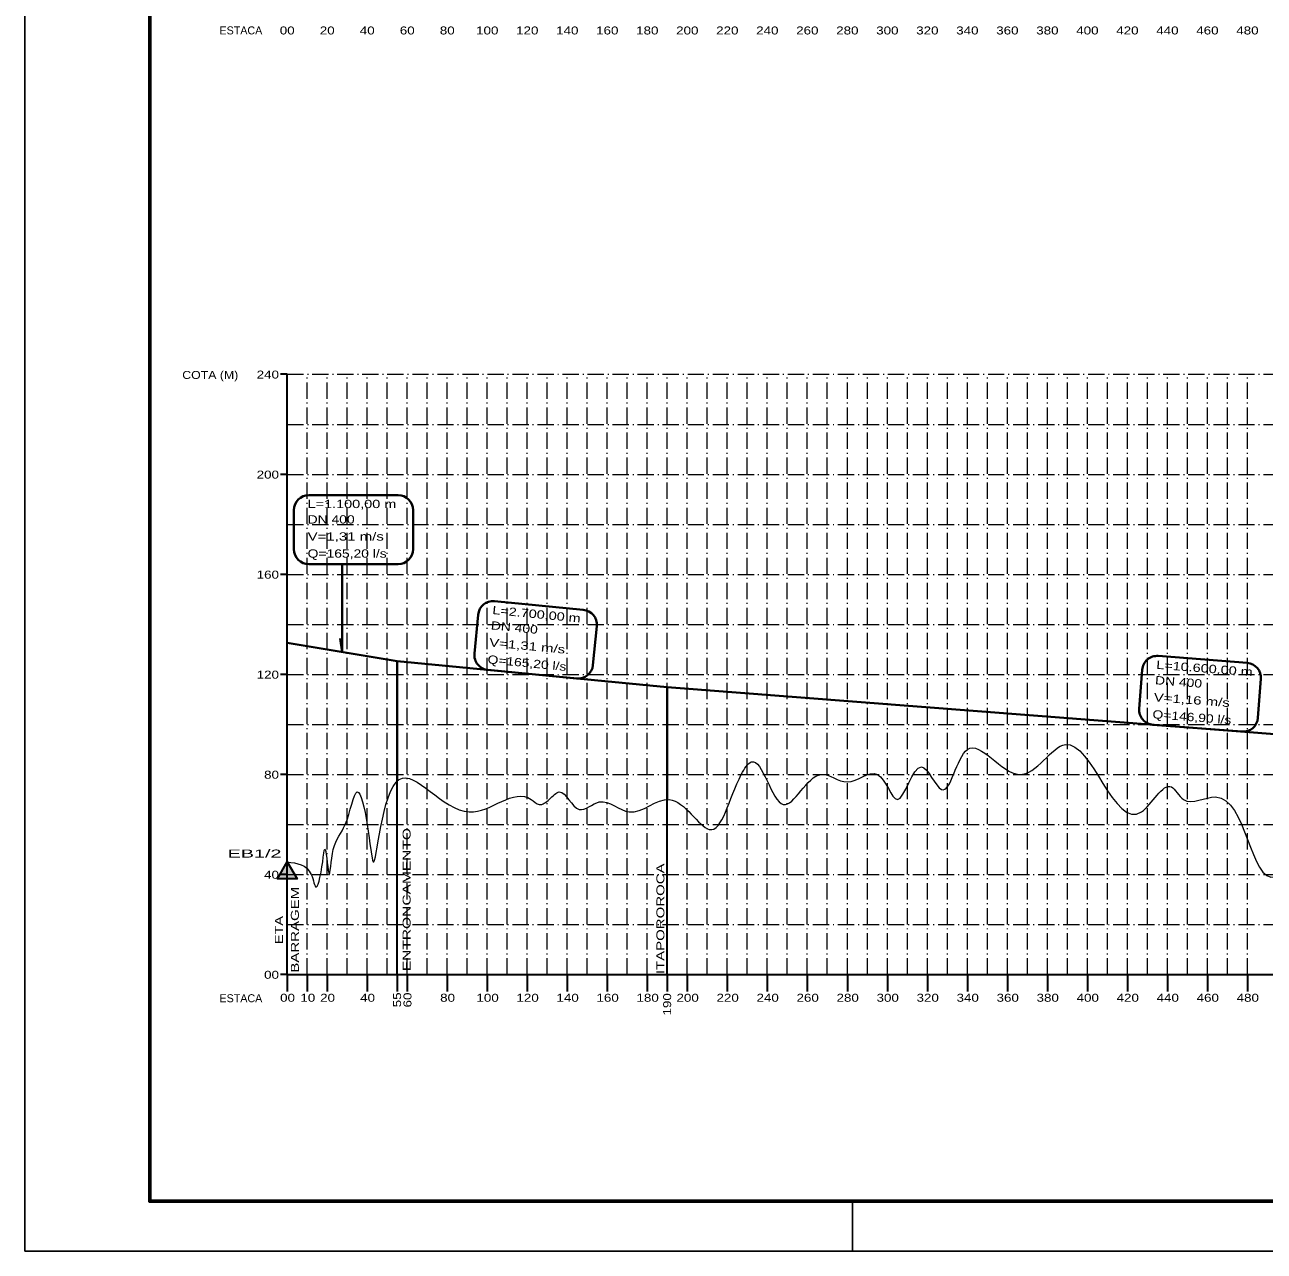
# Model space of a CAD drawing. Extents: x 0 to 1682, y 0 to 1188.
# Drawn here: x -0.2 to 495.5, y -0.1 to 490.3 of the extents above; entities that cross this region are included whole.
import ezdxf
from ezdxf.enums import TextEntityAlignment as Align

# ---------------------------------------------------------------- set-up
doc = ezdxf.new("R2010")
doc.units = 0
doc.header["$LTSCALE"] = 1.3
doc.linetypes.add('DOT_DASHED', pattern=[7.7, 5, -1.2, 0.3, -1.2])
for name, color, linetype, lineweight in [('1', 7, 'DOT_DASHED', 13), ('56', 7, 'Continuous', 13), ('62', 7, 'Continuous', 13), ('63', 7, 'Continuous', 25), ('9', 7, 'Continuous', 40)]:
    doc.layers.add(name, color=color, linetype=linetype, lineweight=lineweight)
doc.layers.add('24', color=7, linetype='Continuous')

msp = doc.modelspace()

# ---------------------------------------------------------------- hatches: boundary and pattern name
at = {"layer": '62'}
msp.add_hatch(color=256, dxfattribs=at).paths.add_polyline_path([(104.775, 155.521), (108.721, 148.783), (100.912, 148.734)])

# ---------------------------------------------------------------- linework, layer by layer
at = {"layer": '1'}
for p, q in [((104.775, 350.521), (1145.575, 350.521)), ((112.775, 110.521), (112.775, 350.521)), ((120.775, 110.521), (120.775, 350.521)), ((128.775, 110.521), (128.775, 350.521)), ((136.775, 110.521), (136.775, 350.521)), ((144.775, 110.521), (144.775, 350.521)), ((152.775, 110.521), (152.775, 350.521)), ((160.775, 110.521), (160.775, 350.521)), ((168.775, 110.521), (168.775, 350.521)), ((176.775, 110.521), (176.775, 350.521)), ((184.775, 110.521), (184.775, 350.521)), ((192.775, 110.521), (192.775, 350.521)), ((200.775, 110.521), (200.775, 350.521)), ((208.775, 110.521), (208.775, 350.521)), ((216.775, 110.521), (216.775, 350.521)), ((224.775, 110.521), (224.775, 350.521)), ((232.775, 110.521), (232.775, 350.521)), ((240.775, 110.521), (240.775, 350.521)), ((248.775, 110.521), (248.775, 350.521)), ((256.775, 110.521), (256.775, 350.521)), ((264.775, 110.521), (264.775, 350.521)), ((272.775, 110.521), (272.775, 350.521)), ((280.775, 110.521), (280.775, 350.521)), ((288.775, 110.521), (288.775, 350.521)), ((296.775, 110.521), (296.775, 350.521)), ((304.775, 110.521), (304.775, 350.521)), ((312.775, 110.521), (312.775, 350.521)), ((320.775, 110.521), (320.775, 350.521)), ((328.775, 110.521), (328.775, 350.521)), ((336.775, 110.521), (336.775, 350.521)), ((344.775, 110.521), (344.775, 350.521)), ((352.775, 110.521), (352.775, 350.521)), ((360.775, 110.521), (360.775, 350.521)), ((368.775, 110.521), (368.775, 350.521)), ((376.775, 110.521), (376.775, 350.521)), ((384.775, 110.521), (384.775, 350.521)), ((392.775, 110.521), (392.775, 350.521)), ((400.775, 110.521), (400.775, 350.521)), ((408.775, 110.521), (408.775, 350.521)), ((416.775, 110.521), (416.775, 350.521)), ((424.775, 110.521), (424.775, 350.521)), ((432.775, 110.521), (432.775, 350.521)), ((440.775, 110.521), (440.775, 350.521)), ((448.775, 110.521), (448.775, 350.521)), ((456.775, 110.521), (456.775, 350.521)), ((464.775, 110.521), (464.775, 350.521)), ((472.775, 110.521), (472.775, 350.521)), ((480.775, 110.521), (480.775, 350.521)), ((488.775, 110.521), (488.775, 350.521)), ((104.775, 330.521), (1145.575, 330.521)), ((104.775, 310.521), (1145.575, 310.521)), ((104.775, 290.521), (1145.575, 290.521)), ((104.775, 270.521), (1145.575, 270.521)), ((104.775, 250.521), (1145.575, 250.521)), ((104.775, 230.521), (1145.575, 230.521)), ((104.775, 210.521), (1145.575, 210.521)), ((104.775, 190.521), (1145.575, 190.521)), ((104.775, 170.521), (1145.575, 170.521)), ((104.775, 150.521), (1145.575, 150.521)), ((104.775, 130.521), (1145.575, 130.521))]:
    msp.add_line(p, q, dxfattribs=at)
at = {"layer": '56'}
msp.add_spline([(104.775, 155.521), (114.375, 150.521), (116.375, 145.521), (117.875, 149.271), (119.975, 160.521), (121.575, 150.521), (123.175, 160.521), (127.975, 170.521), (132.775, 183.521), (136.775, 170.521), (139.175, 155.521), (149.575, 188.521), (177.575, 175.521), (202.375, 180.521), (205.575, 178.521), (209.575, 180.521), (213.575, 183.521), (221.575, 176.521), (229.575, 179.521), (241.575, 175.521), (257.575, 180.521), (273.575, 168.521), (286.375, 190.521), (290.375, 195.521), (303.175, 178.521), (318.375, 190.521), (328.775, 187.521), (340.775, 190.521), (348.775, 180.521), (358.375, 193.521), (366.375, 184.521), (376.775, 200.521), (397.575, 190.521), (415.975, 202.521), (446.375, 175.521), (458.375, 185.521), (463.175, 180.521), (475.975, 181.521), (499.975, 149.521), (508.375, 153.521), (524.375, 150.521), (541.975, 165.521), (561.975, 191.521), (569.975, 180.521), (617.975, 143.521), (647.575, 180.521), (655.975, 185.521), (758.375, 160.521), (767.975, 148.521), (774.375, 155.521), (778.375, 158.521), (790.375, 150.521), (798.375, 156.521), (802.375, 150.521), (818.375, 150.521), (858.375, 140.521), (874.375, 128.521), (898.375, 160.521), (910.375, 145.521), (915.175, 153.521), (935.175, 125.521), (940.775, 130.521), (948.775, 127.521), (956.775, 130.521), (975.975, 120.521), (984.775, 118.521), (995.175, 125.521), (1023.975, 118.521), (1029.575, 120.521), (1033.575, 118.521), (1040.775, 123.521), (1048.775, 118.521), (1068.775, 125.521), (1084.775, 118.521), (1091.175, 123.521), (1095.175, 120.521), (1099.975, 122.521), (1107.975, 117.521), (1114.375, 120.521), (1130.375, 118.521), (1145.575, 118.521)], degree=3, dxfattribs=at)
at = {"layer": '62', "lineweight": 35}
for p, q in [((104.775, 350.521), (102.044, 350.521)), ((104.607, 350.521), (104.775, 350.521)), ((104.775, 110.521), (104.775, 350.521)), ((104.607, 340.521), (104.775, 340.521)), ((104.607, 330.521), (104.775, 330.521)), ((104.607, 320.521), (104.775, 320.521)), ((104.775, 310.521), (102.044, 310.521)), ((104.607, 310.521), (104.775, 310.521)), ((104.607, 300.521), (104.775, 300.521)), ((104.607, 290.521), (104.775, 290.521)), ((104.607, 280.521), (104.775, 280.521)), ((104.775, 270.521), (102.044, 270.521)), ((104.607, 270.521), (104.775, 270.521)), ((104.607, 260.521), (104.775, 260.521)), ((104.607, 250.521), (104.775, 250.521)), ((104.607, 240.521), (104.775, 240.521)), ((104.775, 230.521), (102.044, 230.521)), ((104.607, 230.521), (104.775, 230.521)), ((104.607, 220.521), (104.775, 220.521)), ((104.607, 210.521), (104.775, 210.521)), ((104.607, 200.521), (104.775, 200.521)), ((104.775, 190.521), (102.044, 190.521)), ((104.607, 190.521), (104.775, 190.521)), ((148.775, 110.521), (148.775, 188.469)), ((104.607, 180.521), (104.775, 180.521)), ((256.775, 110.521), (256.775, 180.457)), ((104.607, 170.521), (104.775, 170.521)), ((104.607, 160.521), (104.775, 160.521)), ((104.775, 150.521), (102.044, 150.521)), ((104.607, 150.521), (104.775, 150.521)), ((104.607, 140.521), (104.775, 140.521)), ((104.607, 130.521), (104.775, 130.521)), ((104.607, 120.521), (104.775, 120.521)), ((104.775, 110.521), (102.044, 110.521)), ((104.775, 110.521), (104.775, 103.693)), ((104.775, 110.521), (1145.575, 110.521)), ((112.775, 110.521), (112.775, 103.693)), ((120.775, 110.521), (120.775, 103.693)), ((136.775, 110.521), (136.775, 103.693)), ((148.775, 110.521), (148.775, 103.693)), ((152.775, 110.521), (152.775, 103.693)), ((168.775, 110.521), (168.775, 103.693)), ((184.775, 110.521), (184.775, 103.693)), ((200.775, 110.521), (200.775, 103.693)), ((216.775, 110.521), (216.775, 103.693)), ((232.775, 110.521), (232.775, 103.693)), ((248.775, 110.521), (248.775, 103.693)), ((256.775, 110.521), (256.775, 103.693)), ((264.775, 110.521), (264.775, 103.693)), ((280.775, 110.521), (280.775, 103.693)), ((296.775, 110.521), (296.775, 103.693)), ((312.775, 110.521), (312.775, 103.693)), ((328.775, 110.521), (328.775, 103.693)), ((344.775, 110.521), (344.775, 103.693)), ((360.775, 110.521), (360.775, 103.693)), ((376.775, 110.521), (376.775, 103.693)), ((392.775, 110.521), (392.775, 103.693)), ((408.775, 110.521), (408.775, 103.693)), ((424.775, 110.521), (424.775, 103.693)), ((440.775, 110.521), (440.775, 103.693)), ((456.775, 110.521), (456.775, 103.693)), ((472.775, 110.521), (472.775, 103.693)), ((488.775, 110.521), (488.775, 103.693))]:
    msp.add_line(p, q, dxfattribs=at)
at = {"layer": '62'}
for p, q in [((104.607, 348.521), (104.775, 348.521)), ((104.607, 346.521), (104.775, 346.521)), ((104.607, 344.521), (104.775, 344.521)), ((104.607, 342.521), (104.775, 342.521)), ((104.607, 338.521), (104.775, 338.521)), ((104.607, 336.521), (104.775, 336.521)), ((104.607, 334.521), (104.775, 334.521)), ((104.607, 332.521), (104.775, 332.521)), ((104.607, 328.521), (104.775, 328.521)), ((104.607, 326.521), (104.775, 326.521)), ((104.607, 324.521), (104.775, 324.521)), ((104.607, 322.521), (104.775, 322.521)), ((104.607, 318.521), (104.775, 318.521)), ((104.607, 316.521), (104.775, 316.521)), ((104.607, 314.521), (104.775, 314.521)), ((104.607, 312.521), (104.775, 312.521)), ((104.607, 308.521), (104.775, 308.521)), ((104.607, 306.521), (104.775, 306.521)), ((104.607, 304.521), (104.775, 304.521)), ((104.607, 302.521), (104.775, 302.521)), ((104.607, 298.521), (104.775, 298.521)), ((104.607, 296.521), (104.775, 296.521)), ((104.607, 294.521), (104.775, 294.521)), ((104.607, 292.521), (104.775, 292.521)), ((104.607, 288.521), (104.775, 288.521)), ((104.607, 286.521), (104.775, 286.521)), ((104.607, 284.521), (104.775, 284.521)), ((104.607, 282.521), (104.775, 282.521)), ((104.607, 278.521), (104.775, 278.521)), ((104.607, 276.521), (104.775, 276.521)), ((104.607, 274.521), (104.775, 274.521)), ((104.607, 272.521), (104.775, 272.521)), ((104.607, 268.521), (104.775, 268.521)), ((104.607, 266.521), (104.775, 266.521)), ((104.607, 264.521), (104.775, 264.521)), ((104.607, 262.521), (104.775, 262.521)), ((104.607, 258.521), (104.775, 258.521)), ((104.607, 256.521), (104.775, 256.521)), ((104.607, 254.521), (104.775, 254.521)), ((104.607, 252.521), (104.775, 252.521)), ((104.607, 248.521), (104.775, 248.521)), ((104.607, 246.521), (104.775, 246.521)), ((104.607, 244.521), (104.775, 244.521)), ((104.607, 242.521), (104.775, 242.521)), ((104.607, 238.521), (104.775, 238.521)), ((104.607, 236.521), (104.775, 236.521)), ((104.607, 234.521), (104.775, 234.521)), ((104.607, 232.521), (104.775, 232.521)), ((104.607, 228.521), (104.775, 228.521)), ((104.607, 226.521), (104.775, 226.521)), ((104.607, 224.521), (104.775, 224.521)), ((104.607, 222.521), (104.775, 222.521)), ((104.607, 218.521), (104.775, 218.521)), ((104.607, 216.521), (104.775, 216.521)), ((104.607, 214.521), (104.775, 214.521)), ((104.607, 212.521), (104.775, 212.521)), ((104.607, 208.521), (104.775, 208.521)), ((104.607, 206.521), (104.775, 206.521)), ((104.607, 204.521), (104.775, 204.521)), ((104.607, 202.521), (104.775, 202.521)), ((104.607, 198.521), (104.775, 198.521)), ((104.607, 196.521), (104.775, 196.521)), ((104.607, 194.521), (104.775, 194.521)), ((104.607, 192.521), (104.775, 192.521)), ((104.607, 188.521), (104.775, 188.521)), ((104.607, 186.521), (104.775, 186.521)), ((104.607, 184.521), (104.775, 184.521)), ((104.607, 182.521), (104.775, 182.521)), ((104.607, 178.521), (104.775, 178.521)), ((104.607, 176.521), (104.775, 176.521)), ((104.607, 174.521), (104.775, 174.521)), ((104.607, 172.521), (104.775, 172.521)), ((104.607, 168.521), (104.775, 168.521)), ((104.607, 166.521), (104.775, 166.521)), ((104.607, 164.521), (104.775, 164.521)), ((104.607, 162.521), (104.775, 162.521)), ((104.607, 158.521), (104.775, 158.521)), ((104.607, 156.521), (104.775, 156.521)), ((104.607, 154.521), (104.775, 154.521)), ((104.607, 152.521), (104.775, 152.521)), ((104.607, 148.521), (104.775, 148.521)), ((104.607, 146.521), (104.775, 146.521)), ((104.607, 144.521), (104.775, 144.521)), ((104.607, 142.521), (104.775, 142.521)), ((104.607, 138.521), (104.775, 138.521)), ((104.607, 136.521), (104.775, 136.521)), ((104.607, 134.521), (104.775, 134.521)), ((104.607, 132.521), (104.775, 132.521)), ((104.607, 128.521), (104.775, 128.521)), ((104.607, 126.521), (104.775, 126.521)), ((104.607, 124.521), (104.775, 124.521)), ((104.607, 122.521), (104.775, 122.521)), ((104.607, 118.521), (104.775, 118.521)), ((104.607, 116.521), (104.775, 116.521)), ((104.607, 114.521), (104.775, 114.521)), ((104.607, 112.521), (104.775, 112.521))]:
    msp.add_line(p, q, dxfattribs=at)
at = {"layer": '62', "lineweight": 35}
msp.add_lwpolyline([(104.775, 155.521), (108.721, 148.783), (100.912, 148.734)], close=True, dxfattribs=at)
at = {"layer": '63'}
for p, q in [((-0.168, -0.119), (-0.168, 1187.881)), ((330.832, -0.119), (330.832, 19.881))]:
    msp.add_line(p, q, dxfattribs=at)
at = {"layer": '63', "lineweight": 60}
msp.add_line((1661.832, 19.881), (49.832, 19.881), dxfattribs=at)
at = {"layer": '63'}
for points in [[(-0.168, -0.119), (1681.832, -0.119), (1681.832, 1187.881)], [(-0.168, -0.119), (1681.832, -0.119), (-0.168, -0.119)]]:
    msp.add_lwpolyline(points, dxfattribs=at)
at = {"layer": '63', "lineweight": 60}
msp.add_lwpolyline([(951.544, 19.881), (49.832, 19.881), (49.832, 1167.881)], dxfattribs=at)
at = {"layer": '9'}
for p, q in [((113.46, 302.216), (149.094, 302.216)), ((107.46, 296.216), (107.46, 280.606)), ((155.094, 296.216), (155.094, 280.606)), ((113.46, 274.606), (149.094, 274.606)), ((187.705, 259.801), (223.173, 256.363)), ((181.154, 254.408), (179.648, 238.871)), ((228.566, 249.812), (227.06, 234.274)), ((148.775, 235.835), (148.775, 188.469)), ((453.134, 237.91), (488.663, 235.169)), ((185.041, 232.32), (220.509, 228.881)), ((446.69, 232.389), (445.49, 216.825)), ((494.183, 228.726), (492.983, 213.162)), ((256.775, 180.457), (256.775, 225.365)), ((451.011, 210.382), (486.539, 207.641))]:
    msp.add_line(p, q, dxfattribs=at)
for points in [[(125.943, 244.905), (126.775, 239.47), (126.775, 274.606)], [(104.775, 243.105), (148.775, 235.835), (256.775, 225.365), (680.775, 192.657), (816.775, 182.165), (1145.575, 145.975)]]:
    msp.add_lwpolyline(points, dxfattribs=at)
for centre, start, end in [((113.46, 296.216), 90, 180), ((149.094, 296.216), 0, 90), ((113.46, 280.606), 180, 270), ((149.094, 280.606), 270, 0), ((187.126, 253.829), 84.4628, 174.4628), ((222.594, 250.391), 354.4628, 84.4628), ((185.62, 238.292), 174.4628, 264.4628), ((452.673, 231.928), 85.58878, 175.58878), ((221.088, 234.853), 264.4628, 354.4628), ((488.201, 229.187), 355.58878, 85.58878), ((451.472, 216.364), 175.58877, 265.58877), ((487, 213.623), 265.58877, 355.58877)]:
    msp.add_arc(centre, 6, start, end, dxfattribs=at)

# ---------------------------------------------------------------- texts
at = {"layer": '24'}
for p in [(86.25, 486.45), (86.25, 99.433)]:
    msp.add_text('ESTACA', height=3.2, dxfattribs=at).set_placement(p, align=Align.CENTER)
at = {"layer": '24', "width": 1.25}
for s, p in [('00', (104.775, 486.422)), ('20', (120.775, 486.422)), ('40', (136.775, 486.422)), ('60', (152.775, 486.422)), ('80', (168.775, 486.422)), ('100', (184.775, 486.422)), ('120', (200.775, 486.422)), ('140', (216.775, 486.422)), ('160', (232.775, 486.422)), ('180', (248.775, 486.422)), ('200', (264.775, 486.422)), ('220', (280.775, 486.422)), ('240', (296.775, 486.422)), ('260', (312.775, 486.422)), ('280', (328.775, 486.422)), ('300', (344.775, 486.422)), ('320', (360.775, 486.422)), ('340', (376.775, 486.422)), ('360', (392.775, 486.422)), ('380', (408.775, 486.422)), ('400', (424.775, 486.422)), ('420', (440.775, 486.422)), ('440', (456.775, 486.422)), ('460', (472.775, 486.422)), ('480', (488.775, 486.422)), ('00', (104.915, 99.629)), ('10', (113.007, 99.629)), ('20', (120.915, 99.629)), ('40', (136.915, 99.629)), ('80', (168.915, 99.629)), ('100', (184.915, 99.629)), ('120', (200.915, 99.629)), ('140', (216.915, 99.629)), ('160', (232.915, 99.629)), ('180', (248.915, 99.629)), ('200', (264.915, 99.629)), ('220', (280.915, 99.629)), ('240', (296.915, 99.629)), ('260', (312.915, 99.629)), ('280', (328.915, 99.629)), ('300', (344.915, 99.629)), ('320', (360.915, 99.629)), ('340', (376.915, 99.629)), ('360', (392.915, 99.629)), ('380', (408.915, 99.629)), ('400', (424.915, 99.629)), ('420', (440.915, 99.629)), ('440', (456.915, 99.629)), ('460', (472.915, 99.629)), ('480', (488.915, 99.629))]:
    msp.add_text(s, height=3.2, dxfattribs=at).set_placement(p, align=Align.CENTER)
at = {"layer": '24'}
for s, width, p in [('COTA (M)', 1.15, (85.214, 348.665)), ('240', 1.25, (101.486, 348.819)), ('200', 1.25, (101.486, 308.819)), ('160', 1.25, (101.486, 268.819)), ('120', 1.25, (101.486, 228.819)), ('80', 1.25, (101.486, 188.819)), ('40', 1.25, (101.486, 148.819)), ('00', 1.25, (101.486, 108.819))]:
    msp.add_text(s, height=3.2, dxfattribs=dict(at, width=width)).set_placement(p, align=Align.RIGHT)
for s, width, p in [('ENTRONCAMENTO', 1.45, (154.132, 111.865)), ('ITAPOROROCA', 1.4, (255.616, 110.669)), ('BARRAGEM', 1.4, (109.445, 111.281)), ('ETA', 1.35, (103.06, 122.687))]:
    msp.add_text(s, height=3.2, rotation=90, dxfattribs=dict(at, width=width)).set_placement(p)
at = {"layer": '24', "width": 1.85}
msp.add_text('EB1/2', height=3.2, dxfattribs=at).set_placement((80.927, 157.288))
at = {"layer": '24', "width": 1.25}
for s, p in [('55', (150.311, 100.393)), ('60', (154.464, 100.33)), ('190', (258.315, 98.592))]:
    msp.add_text(s, height=3.2, rotation=90, dxfattribs=at).set_placement(p, align=Align.CENTER)
at = {"layer": '9'}
for s, width, p in [('L=1.100,00 m', 1.3, (112.945, 297.038)), ('DN 400', 1.25, (112.945, 290.858)), ('V=1,31 m/s', 1.35, (112.945, 284.034)), ('Q=165,20 l/s', 1.25, (112.945, 277.211))]:
    msp.add_text(s, height=3.319, dxfattribs=dict(at, width=width)).set_placement(p)
for s, rotation, width, p in [('L=2.700,00 m', 354.463, 1.3, (186.693, 254.697)), ('DN 400', 354.463, 1.25, (186.096, 248.546)), ('V=1,31 m/s', 354.463, 1.35, (185.438, 241.754)), ('Q=165,20 l/s', 354.463, 1.25, (184.779, 234.962)), ('L=10.600,00 m', 355.589, 1.3, (452.222, 232.787)), ('DN 400', 355.589, 1.25, (451.747, 226.625)), ('V=1,16 m/s', 355.589, 1.35, (451.222, 219.822)), ('Q=146,90 l/s', 355.589, 1.25, (450.697, 213.018))]:
    msp.add_text(s, height=3.319, rotation=rotation, dxfattribs=dict(at, width=width)).set_placement(p)

doc.saveas('drawing.dxf')
